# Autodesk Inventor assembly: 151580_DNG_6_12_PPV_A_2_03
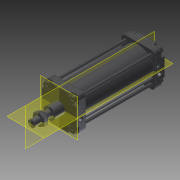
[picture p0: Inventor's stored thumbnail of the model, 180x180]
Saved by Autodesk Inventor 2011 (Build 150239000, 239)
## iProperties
Created: 2012-07
Part Number: 151580_DNG_6_12_PPV_A_2_03
Document SubType Name: Assembly
Designer: R.JANSSEN
Author: R.JANSSEN
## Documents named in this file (4)
- P:\RMD Work Directories\3597 - Areva YC packaging system\Design\CAD\Purchased Parts\FESTO\151580_DNG_6_12_PPV_A_2_03\151580_DNG_6_12_PPV_A_2_03.iam
- P:\RMD Work Directories\3597 - Areva YC packaging system\Design\CAD\Purchased Parts\FESTO\151580_DNG_6_12_PPV_A_2_03\1.ipt
- P:\RMD Work Directories\3597 - Areva YC packaging system\Design\CAD\Purchased Parts\FESTO\151580_DNG_6_12_PPV_A_2_03\2.ipt
- P:\RMD Work Directories\3597 - Areva YC packaging system\Design\CAD\Purchased Parts\FESTO\151580_DNG_6_12_PPV_A_2_03\3.ipt
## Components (3 placed, 3 different names)
1. 1:1 — Mate:1, Angle:1, Mate:4, Mate:5, Mate:6
2. 2:1 — Mate:1, Mate:2, Mate:3, Angle:1, Angle:2, Mate:4, Mate:5, Mate:6
3. 3:1 — Mate:2, Mate:3, Angle:2
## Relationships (8: Mate 6, Angle 2)
- Mate:1: 1:1 ↔ 2:1
- Mate:2: 2:1 ↔ 3:1
- Mate:3: 2:1 ↔ 3:1
- Angle:1: 1:1 ↔ 2:1
- Angle:2: 2:1 ↔ 3:1
- Mate:4: 1:1 ↔ 2:1
- Mate:5: 1:1 ↔ 2:1
- Mate:6: 1:1 ↔ 2:1
